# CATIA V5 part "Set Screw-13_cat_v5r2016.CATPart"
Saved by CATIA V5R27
Part number: Set Screw-13
Bounding box of the stored display mesh (mm): x -5.357 to 5.357, y -5.448 to 5.448, z -1.732 to 14.95
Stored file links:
  E:\_Deepak\2017_Deepak\CATIA\Resources\Tutorial Files\Tutorials\c13_catia_v5_6r2016_tut\c13tut2\c13tut02.CATParts\Set Screw-13_cat_v5r2016.CATPart
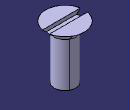
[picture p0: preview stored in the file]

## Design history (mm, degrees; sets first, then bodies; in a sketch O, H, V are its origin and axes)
Body1 (main body)
  Sketch1 on yz-plane, origin (0, 0, 0), H (0, 1, 0), V (0, 0, 1)
    point P1 (0, -1.7321)
    line L1 (0, -1.7321) -> (3, 0)
    point P2 (3, 0)
    line L2 (3, 0) -> (3, 12.5)
    line L3 (3, 12.5) -> (5.45, 14.95)
    point P4 (5.45, 14.95)
    line L4 (5.45, 14.95) -> (0, 14.95)
    point P5 (0, 14.95)
    line L5 (0, 14.95) -> (0, -1.7321)
    length L2 = 12.5
    distance L2 L5 = 3
    distance P4 L5 = 5.45
    angle L3 L5 = 45
    angle L1 L5 = 60
    coincidence: P1 V, P2 H, P5 V
    vertical: L2 V, L5 V
    horizontal: L4 H
  Shaft1: profile Sketch1, axis edge of Sketch1, angle 360
  Sketch2 on yz-plane, origin (0, 0, 0), H (0, 1, 0), V (0, 0, 1)
    line L1 (-1, 14.95) -> (1, 14.95)
    line L2 (1, 14.95) -> (1, 13.95)
    line L3 (1, 13.95) -> (-1, 13.95)
    line L4 (-1, 13.95) -> (-1, 14.95)
    reference projected line E1 (5.45, 14.95) -> (-5.45, 14.95) from edge of Shaft1
    distance V L2 = 1
    length L1 = 2
    length L2 = 1
    horizontal: L1 H, L3 H
    vertical: L2 V, L4 V
    coincidence: L1 E1
  Pocket1: profile Sketch2, direction (-1, 0, 0), length 16, mirrored extent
